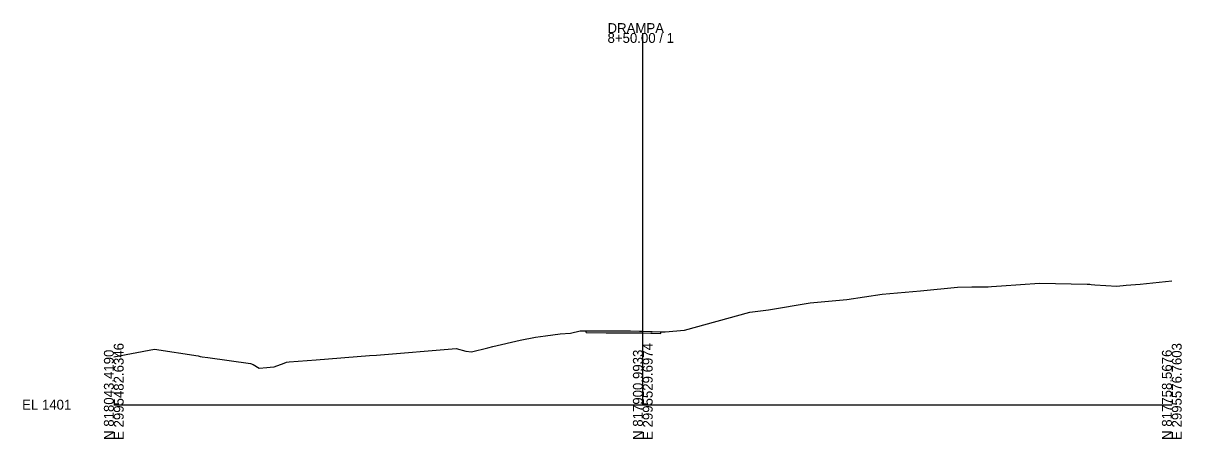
# Model space of a CAD drawing. Extents: x 124 to 2995752, y -10 to 818184.
# Drawn here: x 124.3 to 452.8, y -9.7 to 108.2 of the extents above; entities that cross this region are included whole.
import ezdxf

# ---------------------------------------------------------------- set-up
doc = ezdxf.new("R2010")
doc.units = 0
for name, color, linetype in [('DESIGN - SHEET - Light Grid', 7, 'Continuous'), ('SURVEY - GROUND - Existing Pavement Layer', 7, 'Continuous'), ('SURVEY - GROUND - Top of Ground', 7, 'Continuous')]:
    doc.layers.add(name, color=color, linetype=linetype)

msp = doc.modelspace()

# ---------------------------------------------------------------- linework, layer by layer
at = {"layer": 'DESIGN - SHEET - Light Grid'}
for p, q in [((300, 0), (300, 105.43)), ((150, 0), (300, 0)), ((300, 0), (450, 0))]:
    msp.add_line(p, q, dxfattribs=at)
at = {"layer": 'SURVEY - GROUND - Existing Pavement Layer'}
for p, q in [((283.98, 20.46), (283.98, 20.96)), ((305.13, 20.18), (305.13, 20.68))]:
    msp.add_line(p, q, dxfattribs=at)
msp.add_lwpolyline([(283.98, 20.46), (289.6, 20.42), (292.88, 20.4), (296.49, 20.41), (299.11, 20.39), (300, 20.36), (302.27, 20.29), (302.63, 20.24), (305.13, 20.18)], dxfattribs=at)
at = {"layer": 'SURVEY - GROUND - Top of Ground'}
msp.add_lwpolyline([(150, 13.61), (161.59, 15.72), (173.89, 13.83), (174.52, 13.69), (175.05, 13.6), (176.68, 13.38), (188.75, 11.71), (189.52, 11.44), (191.19, 10.33), (193.39, 10.54), (194.37, 10.63), (195.51, 10.73), (198.28, 11.8), (198.96, 12.05), (199.72, 12.14), (207.4, 12.72), (222.54, 13.91), (224.5, 14.05), (247.12, 15.93), (249.81, 15.22), (251.41, 14.96), (256.08, 16.17), (257.46, 16.53), (265.25, 18.3), (269.54, 19.11), (272.44, 19.49), (276.59, 20.11), (279.47, 20.24), (282.27, 20.98), (283.37, 20.96), (283.98, 20.96), (289.6, 20.92), (292.88, 20.9), (296.49, 20.91), (299.11, 20.89), (300, 20.86), (302.27, 20.79), (302.63, 20.74), (305.13, 20.68), (305.47, 20.68), (306.37, 20.68), (311.78, 21.11), (330.36, 26.28), (335.61, 26.94), (347.41, 28.9), (357.82, 29.79), (367.91, 31.34), (378.73, 32.29), (389.25, 33.3), (393.27, 33.4), (397.89, 33.45), (398.83, 33.55), (401.75, 33.76), (412.48, 34.49), (426, 34.14), (426.73, 34.15), (427.17, 34.13), (428.17, 34.03), (434.39, 33.65), (437.09, 33.94), (440.99, 34.17), (450, 35.14)], dxfattribs=at)

# ---------------------------------------------------------------- texts
at = {"layer": 'DESIGN - SHEET - Light Grid'}
for s, p in [('8+50.00 / 1', (290, 102.63)), ('DRAMPA', (290, 105.43)), ('EL 1401', (124, -1.4))]:
    msp.add_text(s, height=2.8, dxfattribs=at).set_placement(p)
for s, p in [('E 2995482.6346', (152.8, -10)), ('E 2995529.6974', (302.8, -10)), ('E 2995576.7603', (452.8, -10)), ('N 818043.4190', (150, -10)), ('N 817900.9933', (300, -10)), ('N 817758.5676', (450, -10))]:
    msp.add_text(s, height=2.8, rotation=90, dxfattribs=at).set_placement(p)

doc.saveas('drawing.dxf')
